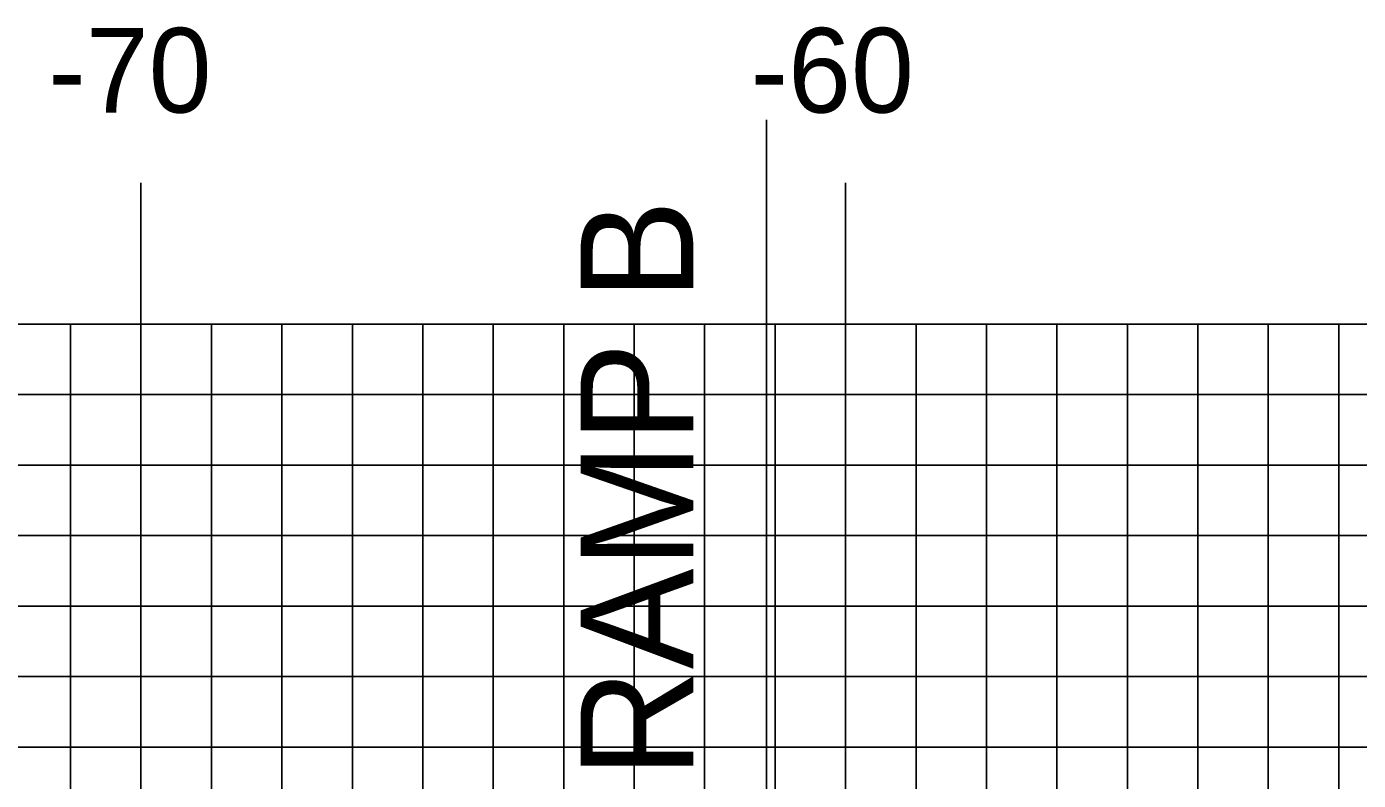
# Model space of a CAD drawing. Extents: x 853894 to 854237, y 366605 to 366825.
# Drawn here: x 853987.91 to 854006.81, y 366771.58 to 366782.27 of the extents above; entities that cross this region are included whole.
import ezdxf

# ---------------------------------------------------------------- set-up
doc = ezdxf.new("R2010")
doc.units = 0
for name, color, linetype in [('ANNOTATION', 7, 'Continuous'), ('D_Roadway_SubGrade', 7, 'Continuous'), ('H_V ANNOTATION', 7, 'Continuous'), ('MAJOR', 7, 'Continuous'), ('MINOR', 7, 'Continuous')]:
    doc.layers.add(name, color=color, linetype=linetype)

msp = doc.modelspace()

# ---------------------------------------------------------------- linework, layer by layer
at = {"layer": 'D_Roadway_SubGrade'}
msp.add_line((853998.41, 366780.952), (853998.41, 366763.18), dxfattribs=at)
at = {"layer": 'MAJOR'}
for p, q in [((853989.53, 366780.059), (853989.53, 366778.055)), ((853999.53, 366780.059), (853999.53, 366778.055)), ((853919.53, 366778.055), (854199.53, 366778.055)), ((853919.53, 366778.055), (854199.53, 366778.055)), ((853989.53, 366753.055), (853989.53, 366778.055)), ((853999.53, 366753.055), (853999.53, 366778.055)), ((853919.53, 366773.055), (854199.53, 366773.055))]:
    msp.add_line(p, q, dxfattribs=at)
at = {"layer": 'MINOR'}
for p, q in [((853988.53, 366753.055), (853988.53, 366778.055)), ((853990.53, 366753.055), (853990.53, 366778.055)), ((853991.53, 366753.055), (853991.53, 366778.055)), ((853992.53, 366753.055), (853992.53, 366778.055)), ((853993.53, 366753.055), (853993.53, 366778.055)), ((853994.53, 366753.055), (853994.53, 366778.055)), ((853995.53, 366753.055), (853995.53, 366778.055)), ((853996.53, 366753.055), (853996.53, 366778.055)), ((853997.53, 366753.055), (853997.53, 366778.055)), ((853998.53, 366753.055), (853998.53, 366778.055)), ((854000.53, 366753.055), (854000.53, 366778.055)), ((854001.53, 366753.055), (854001.53, 366778.055)), ((854002.53, 366753.055), (854002.53, 366778.055)), ((854003.53, 366753.055), (854003.53, 366778.055)), ((854004.53, 366753.055), (854004.53, 366778.055)), ((854005.53, 366753.055), (854005.53, 366778.055)), ((854006.53, 366753.055), (854006.53, 366778.055)), ((853919.53, 366777.055), (854199.53, 366777.055)), ((853919.53, 366776.055), (854199.53, 366776.055)), ((853919.53, 366775.055), (854199.53, 366775.055)), ((853919.53, 366774.055), (854199.53, 366774.055)), ((853919.53, 366772.055), (854199.53, 366772.055))]:
    msp.add_line(p, q, dxfattribs=at)

# ---------------------------------------------------------------- texts
at = {"layer": 'ANNOTATION'}
msp.add_text('RAMP B', height=1.6, rotation=90, dxfattribs=at).set_placement((853997.369, 366771.616))
at = {"layer": 'H_V ANNOTATION'}
for s, p in [('-70', (853988.213, 366781.055)), ('-60', (853998.181, 366781.055))]:
    msp.add_text(s, height=1.2, dxfattribs=at).set_placement(p)

doc.saveas('drawing.dxf')
